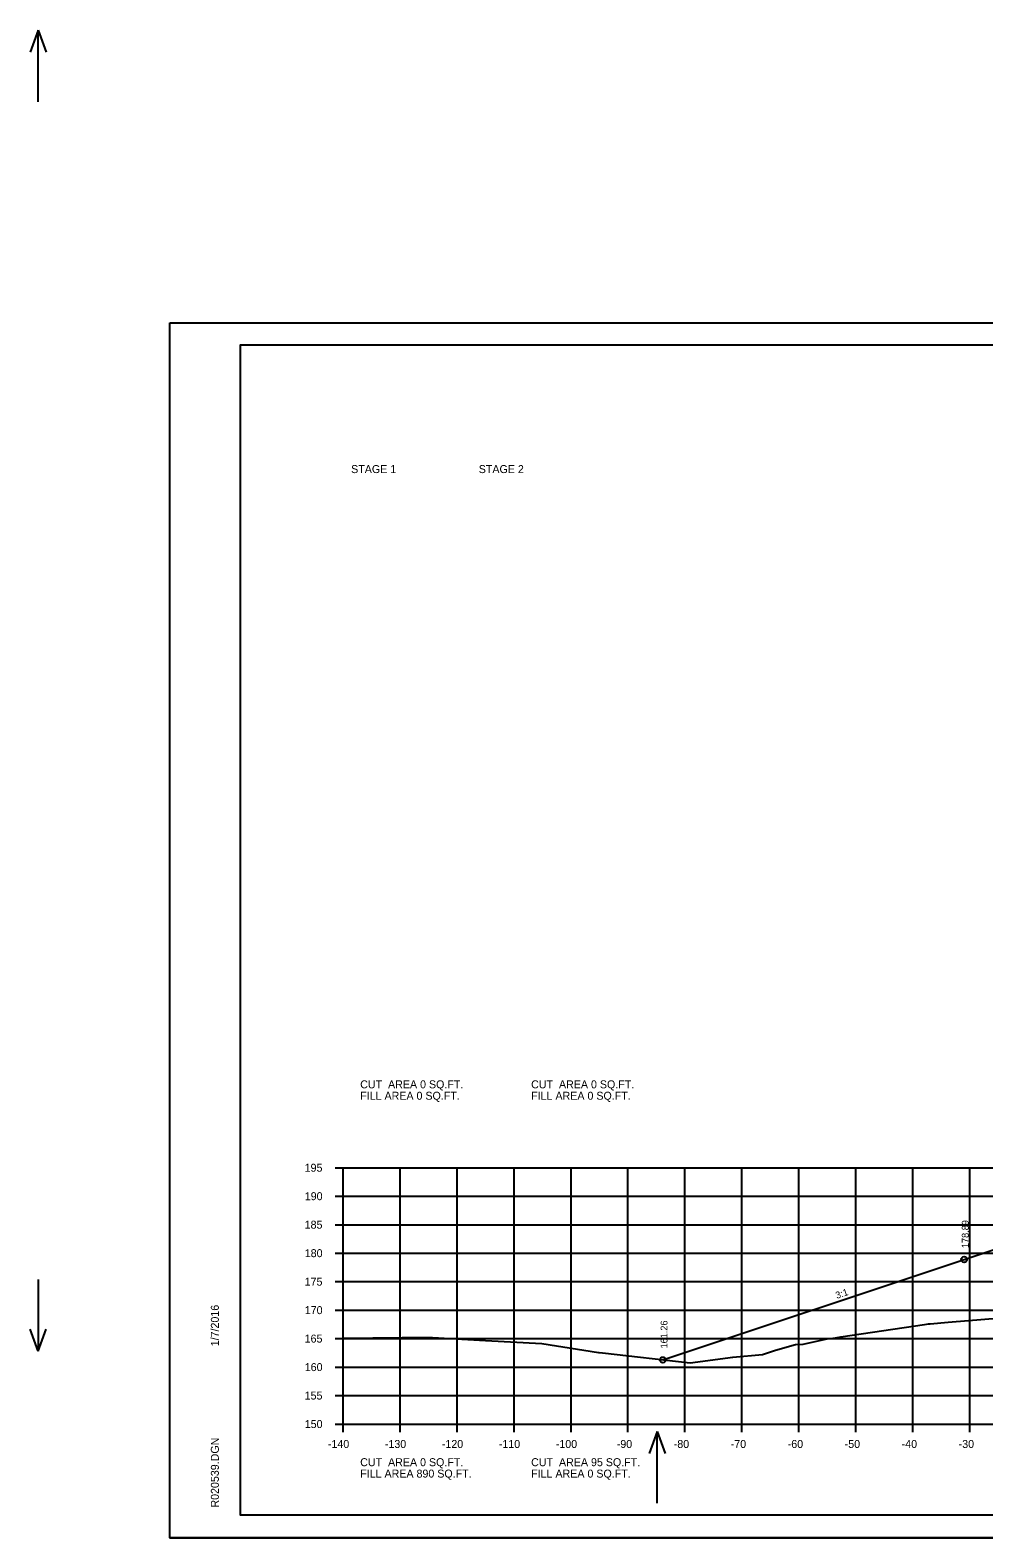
# Model space of a CAD drawing. Extents: x 915787 to 919910, y 133456 to 136717.
# Drawn here: x 916219.1 to 916386.4, y 134736.1 to 135000.8 of the extents above; entities that cross this region are included whole.
import ezdxf

# ---------------------------------------------------------------- set-up
doc = ezdxf.new("R2010")
doc.units = 0
for name, color, linetype in [('R_Axis', 7, 'Continuous'), ('R_Axis Annot', 7, 'Continuous'), ('R_Border', 7, 'Continuous'), ('R_Border Notes', 7, 'Continuous'), ('R_Exist Surface', 7, 'Continuous'), ('R_Fin Surface', 7, 'Continuous'), ('R_Grid', 7, 'Continuous'), ('R_No Plot', 7, 'Continuous'), ('R_Water Annot', 7, 'Continuous'), ('R_Xsect Elev', 7, 'Continuous'), ('R_Xsect Slope', 7, 'Continuous')]:
    doc.layers.add(name, color=color, linetype=linetype)

msp = doc.modelspace()

# ---------------------------------------------------------------- linework, layer by layer
at = {"layer": 'R_Axis'}
for p, q in [((916272.58, 134801.04), (916273.98, 134801.04)), ((916273.98, 134756.04), (916273.98, 134801.04)), ((916272.58, 134796.04), (916273.98, 134796.04)), ((916272.58, 134791.04), (916273.98, 134791.04)), ((916272.58, 134786.04), (916273.98, 134786.04)), ((916272.58, 134781.04), (916273.98, 134781.04)), ((916272.58, 134776.04), (916273.98, 134776.04)), ((916272.58, 134771.04), (916273.98, 134771.04)), ((916272.58, 134766.04), (916273.98, 134766.04)), ((916272.58, 134761.04), (916273.98, 134761.04)), ((916272.58, 134756.04), (916273.98, 134756.04)), ((916273.98, 134756.04), (916553.98, 134756.04)), ((916273.98, 134754.64), (916273.98, 134756.04)), ((916283.98, 134754.64), (916283.98, 134756.04)), ((916293.98, 134754.64), (916293.98, 134756.04)), ((916303.98, 134754.64), (916303.98, 134756.04)), ((916313.98, 134754.64), (916313.98, 134756.04)), ((916323.98, 134754.64), (916323.98, 134756.04)), ((916333.98, 134754.64), (916333.98, 134756.04)), ((916343.98, 134754.64), (916343.98, 134756.04)), ((916353.98, 134754.64), (916353.98, 134756.04)), ((916363.98, 134754.64), (916363.98, 134756.04)), ((916373.98, 134754.64), (916373.98, 134756.04)), ((916383.98, 134754.64), (916383.98, 134756.04))]:
    msp.add_line(p, q, dxfattribs=at)
at = {"layer": 'R_Border'}
for p, q in [((916255.98, 134945.5), (916572.16, 134945.5)), ((916255.98, 134740.04), (916255.98, 134945.5)), ((916255.98, 134740.04), (916255.98, 134740.04)), ((916572.16, 134740.04), (916255.98, 134740.04))]:
    msp.add_line(p, q, dxfattribs=at)
at = {"layer": 'R_Exist Surface'}
msp.add_lwpolyline([(916273.98, 134771.13), (916284.33, 134771.23), (916289.66, 134771.23), (916298.99, 134770.72), (916308.86, 134770.19), (916318.83, 134768.61), (916318.93, 134768.59), (916319.48, 134768.53), (916334.87, 134766.76), (916342.38, 134767.76), (916347.6, 134768.27), (916349.87, 134769), (916353.38, 134769.99), (916354.74, 134770.05), (916358.91, 134771.01), (916360.37, 134771.17), (916361.34, 134771.35), (916376.01, 134773.49), (916376.73, 134773.61), (916377.01, 134773.63), (916380.2, 134773.93), (916401.66, 134775.7)], dxfattribs=at)
at = {"layer": 'R_Fin Surface'}
msp.add_lwpolyline([(916330.11, 134767.31), (916382.97, 134784.93), (916388.22, 134786.68), (916391.47, 134787.76), (916402.97, 134788.22), (916413.97, 134788.44), (916424.97, 134788.22), (916436.47, 134787.76), (916439.73, 134786.68), (916444.97, 134784.93), (916490.39, 134784.15)], dxfattribs=at)
at = {"layer": 'R_Grid'}
for p, q in [((916273.98, 134801.04), (916553.98, 134801.04)), ((916273.98, 134756.04), (916273.98, 134801.04)), ((916283.98, 134756.04), (916283.98, 134801.04)), ((916293.98, 134756.04), (916293.98, 134801.04)), ((916303.98, 134756.04), (916303.98, 134801.04)), ((916313.98, 134756.04), (916313.98, 134801.04)), ((916323.98, 134756.04), (916323.98, 134801.04)), ((916333.98, 134756.04), (916333.98, 134801.04)), ((916343.98, 134756.04), (916343.98, 134801.04)), ((916353.98, 134756.04), (916353.98, 134801.04)), ((916363.98, 134756.04), (916363.98, 134801.04)), ((916373.98, 134756.04), (916373.98, 134801.04)), ((916383.98, 134756.04), (916383.98, 134801.04)), ((916273.98, 134796.04), (916553.98, 134796.04)), ((916273.98, 134791.04), (916553.98, 134791.04)), ((916273.98, 134786.04), (916553.98, 134786.04)), ((916273.98, 134781.04), (916553.98, 134781.04)), ((916273.98, 134776.04), (916553.98, 134776.04)), ((916273.98, 134771.04), (916553.98, 134771.04)), ((916273.98, 134766.04), (916553.98, 134766.04)), ((916273.98, 134761.04), (916553.98, 134761.04)), ((916273.98, 134756.04), (916553.98, 134756.04))]:
    msp.add_line(p, q, dxfattribs=at)
at = {"layer": 'R_No Plot'}
for p, q in [((916243.57, 134949.4), (916576.91, 134949.4)), ((916243.57, 134736.06), (916576.91, 134736.06))]:
    msp.add_line(p, q, dxfattribs=at)
for points in [[(916243.57, 134949.4), (916576.91, 134949.4), (916576.91, 134736.06), (916243.57, 134736.06)], [(916489.9, 134945.5), (916489.9, 134935.62), (916525.63, 134935.62), (916525.63, 134932.7), (916548.83, 134932.7), (916548.83, 134909.49), (916572.16, 134909.49), (916572.16, 134740.04), (916255.98, 134740.04), (916255.98, 134945.5)]]:
    msp.add_lwpolyline(points, close=True, dxfattribs=at)
for centre in [(916382.97, 134784.93), (916382.97, 134784.93), (916330.11, 134767.31), (916330.11, 134767.31)]:
    msp.add_circle(centre, 0.5, dxfattribs=at)
at = {"layer": 'R_Water Annot'}
for p, q in [((916220.45, 135000.76), (916219.05, 134996.92)), ((916220.45, 134988.2), (916220.45, 135000.76)), ((916220.45, 135000.76), (916221.85, 134996.92)), ((916220.45, 134781.42), (916220.45, 134768.85)), ((916220.45, 134768.85), (916219.05, 134772.7)), ((916220.45, 134768.85), (916221.85, 134772.7)), ((916329.11, 134754.72), (916327.71, 134750.87)), ((916329.11, 134742.15), (916329.11, 134754.72)), ((916329.11, 134754.72), (916330.51, 134750.87))]:
    msp.add_line(p, q, dxfattribs=at)

# ---------------------------------------------------------------- texts
at = {"layer": 'R_Axis Annot'}
for s, p in [('195', (916267.23, 134800.34)), ('190', (916267.25, 134795.34)), ('185', (916267.23, 134790.34)), ('180', (916267.25, 134785.34)), ('175', (916267.23, 134780.34)), ('170', (916267.25, 134775.34)), ('165', (916267.23, 134770.34)), ('160', (916267.25, 134765.34)), ('155', (916267.23, 134760.34)), ('150', (916267.25, 134755.34)), ('-140', (916271.31, 134751.84)), ('-130', (916281.31, 134751.84)), ('-120', (916291.31, 134751.84)), ('-110', (916301.31, 134751.84)), ('-100', (916311.31, 134751.84)), ('-90', (916322.01, 134751.84)), ('-80', (916332.01, 134751.84)), ('-70', (916342.01, 134751.84)), ('-60', (916352.01, 134751.84)), ('-50', (916362.01, 134751.84)), ('-40', (916372.01, 134751.84)), ('-30', (916382.01, 134751.84))]:
    msp.add_text(s, height=1.4, dxfattribs=at).set_placement(p)
at = {"layer": 'R_Border'}
for s, p in [('1/7/2016', (916252.17, 134769.69)), ('R020539.DGN', (916252.17, 134741.37))]:
    msp.add_text(s, height=1.4, rotation=90, dxfattribs=at).set_placement(p)
at = {"layer": 'R_Border Notes'}
for s, p in [('STAGE 1', (916275.39, 134923)), ('STAGE 2', (916297.79, 134923)), ('CUT  AREA 0 SQ.FT.', (916276.98, 134814.98)), ('FILL AREA 0 SQ.FT.', (916276.98, 134812.98)), ('CUT  AREA 0 SQ.FT.', (916306.98, 134814.98)), ('FILL AREA 0 SQ.FT.', (916306.98, 134812.98)), ('CUT  AREA 0 SQ.FT.', (916276.98, 134748.64)), ('FILL AREA 890 SQ.FT.', (916276.98, 134746.64)), ('CUT  AREA 95 SQ.FT.', (916306.98, 134748.64)), ('FILL AREA 0 SQ.FT.', (916306.98, 134746.64))]:
    msp.add_text(s, height=1.4, dxfattribs=at).set_placement(p)
at = {"layer": 'R_Xsect Elev'}
for s, p in [('178.89', (916383.77, 134786.93)), ('161.26', (916330.91, 134769.31))]:
    msp.add_text(s, height=1.2, rotation=90, dxfattribs=at).set_placement(p)
at = {"layer": 'R_Xsect Slope'}
msp.add_text('3:1', height=1.2, rotation=18.4349, dxfattribs=at).set_placement((916360.63, 134778.01))

doc.saveas('drawing.dxf')
